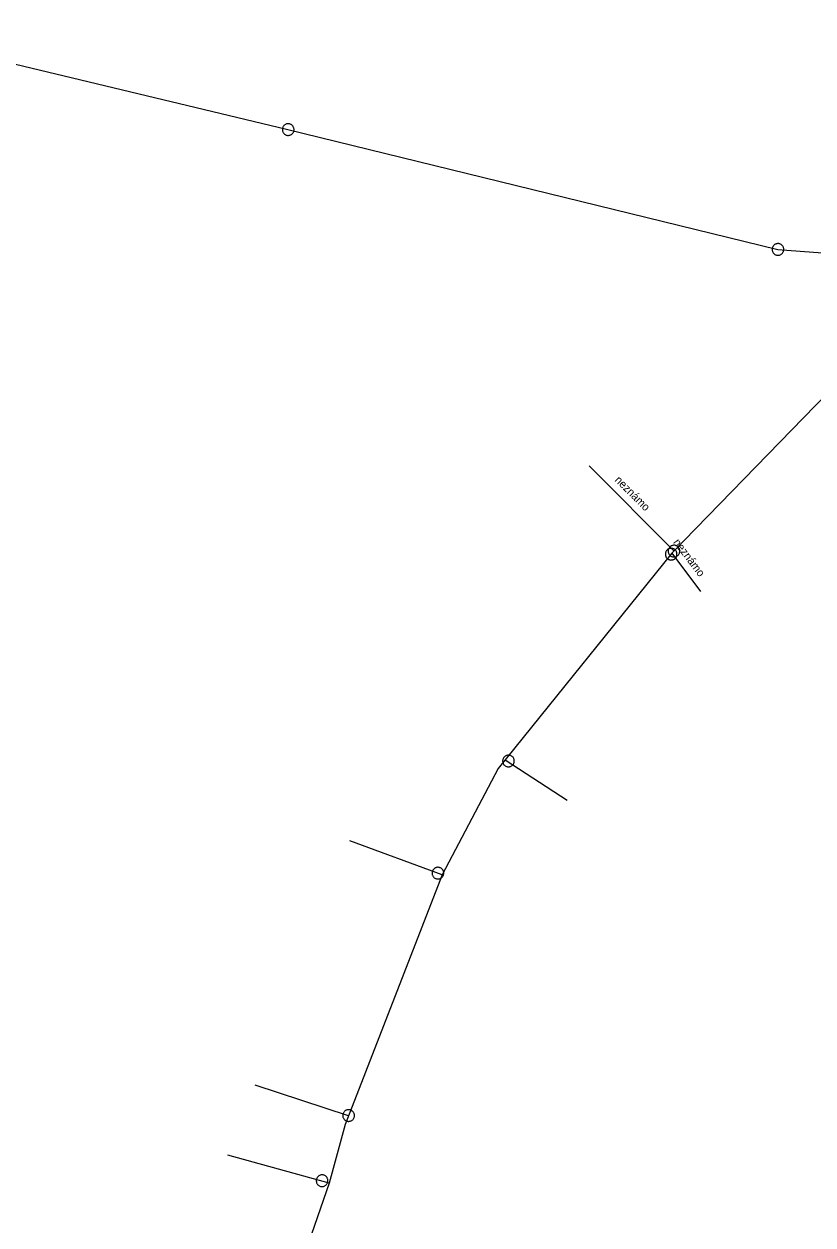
# Model space of a CAD drawing. Extents: x -741806 to -738704, y -1059275 to -1055387.
# Drawn here: x -740279.9 to -740220.6, y -1056767.8 to -1056677.8 of the extents above; entities that cross this region are included whole.
import ezdxf

# ---------------------------------------------------------------- set-up
doc = ezdxf.new("R2010")
doc.units = 0
doc.header["$LTSCALE"] = 0.4
for name, color, linetype, lineweight in [('2', 7, 'Continuous', 25), ('21', 7, 'Continuous', 13), ('3', 7, 'Continuous', 13), ('51', 7, 'Continuous', 13), ('52', 7, 'Continuous', 25)]:
    doc.layers.add(name, color=color, linetype=linetype, lineweight=lineweight)
doc.layers.add('54', color=7, linetype='Continuous')

msp = doc.modelspace()

# ---------------------------------------------------------------- linework, layer by layer
at = {"layer": '2'}
msp.add_lwpolyline([(-740339.62, -1056830), (-740315.66, -1056820.24), (-740310.64, -1056801.08), (-740301.43, -1056762.19), (-740297.32, -1056727.3), (-740286.155, -1056679.426), (-740260.146, -1056685.649), (-740223.28, -1056694.679), (-740203.5, -1056696.159)], dxfattribs=at)
at = {"layer": '21'}
for p, q in [((-740231.074, -1056717.3), (-740237.443, -1056710.901)), ((-740231.234, -1056717.463), (-740229.083, -1056720.327)), ((-740243.752, -1056732.952), (-740239.088, -1056735.977)), ((-740248.473, -1056741.574), (-740255.403, -1056739.044)), ((-740255.507, -1056759.67), (-740262.517, -1056757.362)), ((-740256.949, -1056764.72), (-740264.563, -1056762.608))]:
    msp.add_line(p, q, dxfattribs=at)
at = {"layer": '3'}
for points in [[(-740259.604, -1056685.794), (-740259.596, -1056685.75), (-740259.592, -1056685.704), (-740259.593, -1056685.658), (-740259.599, -1056685.613), (-740259.61, -1056685.568), (-740259.625, -1056685.525), (-740259.644, -1056685.484), (-740259.668, -1056685.444), (-740259.696, -1056685.408), (-740259.727, -1056685.375), (-740259.762, -1056685.345), (-740259.8, -1056685.318), (-740259.84, -1056685.297), (-740259.881, -1056685.278), (-740259.926, -1056685.266), (-740259.971, -1056685.257), (-740260.016, -1056685.254), (-740260.062, -1056685.254), (-740260.108, -1056685.26), (-740260.152, -1056685.271), (-740260.195, -1056685.286), (-740260.236, -1056685.305), (-740260.276, -1056685.329), (-740260.312, -1056685.356), (-740260.346, -1056685.388), (-740260.375, -1056685.423), (-740260.402, -1056685.46), (-740260.424, -1056685.501), (-740260.441, -1056685.543), (-740260.454, -1056685.587), (-740260.463, -1056685.631), (-740260.467, -1056685.677), (-740260.466, -1056685.723), (-740260.46, -1056685.769), (-740260.45, -1056685.813), (-740260.435, -1056685.856), (-740260.415, -1056685.897), (-740260.391, -1056685.937), (-740260.363, -1056685.973), (-740260.332, -1056686.006), (-740260.298, -1056686.036), (-740260.26, -1056686.063), (-740260.22, -1056686.085), (-740260.178, -1056686.103), (-740260.134, -1056686.115), (-740260.089, -1056686.124), (-740260.043, -1056686.128), (-740259.998, -1056686.127), (-740259.952, -1056686.121), (-740259.907, -1056686.11), (-740259.864, -1056686.095), (-740259.823, -1056686.076), (-740259.784, -1056686.052), (-740259.747, -1056686.025), (-740259.714, -1056685.993), (-740259.683, -1056685.958), (-740259.658, -1056685.921), (-740259.636, -1056685.88), (-740259.618, -1056685.838), (-740259.604, -1056685.795)], [(-740222.854, -1056694.783), (-740222.846, -1056694.739), (-740222.842, -1056694.693), (-740222.843, -1056694.647), (-740222.849, -1056694.602), (-740222.86, -1056694.557), (-740222.875, -1056694.514), (-740222.894, -1056694.473), (-740222.918, -1056694.433), (-740222.946, -1056694.397), (-740222.977, -1056694.364), (-740223.012, -1056694.334), (-740223.05, -1056694.307), (-740223.09, -1056694.286), (-740223.131, -1056694.267), (-740223.176, -1056694.255), (-740223.221, -1056694.246), (-740223.266, -1056694.243), (-740223.312, -1056694.243), (-740223.358, -1056694.249), (-740223.402, -1056694.26), (-740223.445, -1056694.275), (-740223.486, -1056694.294), (-740223.526, -1056694.318), (-740223.562, -1056694.345), (-740223.596, -1056694.377), (-740223.625, -1056694.412), (-740223.652, -1056694.449), (-740223.674, -1056694.49), (-740223.691, -1056694.532), (-740223.704, -1056694.576), (-740223.713, -1056694.62), (-740223.717, -1056694.666), (-740223.716, -1056694.712), (-740223.71, -1056694.758), (-740223.7, -1056694.802), (-740223.685, -1056694.845), (-740223.665, -1056694.886), (-740223.641, -1056694.926), (-740223.613, -1056694.962), (-740223.582, -1056694.995), (-740223.548, -1056695.025), (-740223.51, -1056695.052), (-740223.47, -1056695.074), (-740223.428, -1056695.092), (-740223.384, -1056695.104), (-740223.339, -1056695.113), (-740223.293, -1056695.117), (-740223.248, -1056695.116), (-740223.202, -1056695.11), (-740223.157, -1056695.099), (-740223.114, -1056695.084), (-740223.073, -1056695.065), (-740223.034, -1056695.041), (-740222.997, -1056695.014), (-740222.964, -1056694.982), (-740222.933, -1056694.947), (-740222.908, -1056694.91), (-740222.886, -1056694.869), (-740222.868, -1056694.827), (-740222.854, -1056694.784)]]:
    msp.add_lwpolyline(points, dxfattribs=at)
at = {"layer": '51'}
for points in [[(-740231.566, -1056717.875), (-740231.529, -1056717.902), (-740231.49, -1056717.925), (-740231.447, -1056717.944), (-740231.405, -1056717.958), (-740231.36, -1056717.967), (-740231.314, -1056717.972), (-740231.268, -1056717.971), (-740231.222, -1056717.967), (-740231.178, -1056717.957), (-740231.135, -1056717.943), (-740231.092, -1056717.924), (-740231.052, -1056717.902), (-740231.015, -1056717.875), (-740230.981, -1056717.844), (-740230.951, -1056717.81), (-740230.924, -1056717.773), (-740230.901, -1056717.733), (-740230.882, -1056717.692), (-740230.869, -1056717.648), (-740230.859, -1056717.602), (-740230.855, -1056717.557), (-740230.854, -1056717.512), (-740230.859, -1056717.466), (-740230.868, -1056717.421), (-740230.883, -1056717.377), (-740230.902, -1056717.335), (-740230.924, -1056717.297), (-740230.952, -1056717.259), (-740230.982, -1056717.225), (-740231.016, -1056717.194), (-740231.053, -1056717.168), (-740231.093, -1056717.145), (-740231.135, -1056717.126), (-740231.178, -1056717.112), (-740231.223, -1056717.103), (-740231.269, -1056717.098), (-740231.314, -1056717.098), (-740231.36, -1056717.102), (-740231.405, -1056717.113), (-740231.448, -1056717.127), (-740231.49, -1056717.145), (-740231.53, -1056717.168), (-740231.567, -1056717.195), (-740231.601, -1056717.225), (-740231.632, -1056717.26), (-740231.659, -1056717.297), (-740231.681, -1056717.337), (-740231.7, -1056717.378), (-740231.714, -1056717.422), (-740231.723, -1056717.467), (-740231.728, -1056717.513), (-740231.729, -1056717.558), (-740231.723, -1056717.604), (-740231.714, -1056717.648), (-740231.699, -1056717.692), (-740231.681, -1056717.734), (-740231.658, -1056717.773), (-740231.631, -1056717.811), (-740231.6, -1056717.845), (-740231.566, -1056717.874)], [(-740231.385, -1056717.618), (-740231.352, -1056717.648), (-740231.315, -1056717.675), (-740231.274, -1056717.698), (-740231.233, -1056717.715), (-740231.189, -1056717.729), (-740231.143, -1056717.738), (-740231.098, -1056717.742), (-740231.052, -1056717.742), (-740231.007, -1056717.735), (-740230.963, -1056717.726), (-740230.919, -1056717.711), (-740230.877, -1056717.692), (-740230.837, -1056717.669), (-740230.801, -1056717.641), (-740230.768, -1056717.61), (-740230.737, -1056717.575), (-740230.711, -1056717.538), (-740230.688, -1056717.498), (-740230.671, -1056717.456), (-740230.657, -1056717.412), (-740230.649, -1056717.367), (-740230.644, -1056717.322), (-740230.645, -1056717.276), (-740230.65, -1056717.23), (-740230.66, -1056717.185), (-740230.675, -1056717.142), (-740230.694, -1056717.101), (-740230.718, -1056717.061), (-740230.745, -1056717.025), (-740230.776, -1056716.99), (-740230.811, -1056716.961), (-740230.848, -1056716.935), (-740230.888, -1056716.912), (-740230.93, -1056716.894), (-740230.974, -1056716.881), (-740231.019, -1056716.871), (-740231.064, -1056716.868), (-740231.11, -1056716.868), (-740231.156, -1056716.874), (-740231.2, -1056716.884), (-740231.244, -1056716.899), (-740231.286, -1056716.918), (-740231.324, -1056716.942), (-740231.361, -1056716.968), (-740231.395, -1056717), (-740231.426, -1056717.034), (-740231.451, -1056717.072), (-740231.474, -1056717.111), (-740231.492, -1056717.154), (-740231.505, -1056717.198), (-740231.514, -1056717.243), (-740231.519, -1056717.288), (-740231.517, -1056717.334), (-740231.513, -1056717.379), (-740231.502, -1056717.424), (-740231.487, -1056717.468), (-740231.468, -1056717.509), (-740231.444, -1056717.549), (-740231.417, -1056717.585), (-740231.386, -1056717.618)], [(-740243.133, -1056733.285), (-740243.11, -1056733.246), (-740243.092, -1056733.204), (-740243.077, -1056733.16), (-740243.068, -1056733.116), (-740243.063, -1056733.07), (-740243.063, -1056733.024), (-740243.068, -1056732.979), (-740243.077, -1056732.934), (-740243.092, -1056732.891), (-740243.11, -1056732.849), (-740243.133, -1056732.809), (-740243.16, -1056732.771), (-740243.191, -1056732.737), (-740243.225, -1056732.707), (-740243.262, -1056732.68), (-740243.302, -1056732.657), (-740243.343, -1056732.638), (-740243.387, -1056732.624), (-740243.432, -1056732.615), (-740243.478, -1056732.611), (-740243.523, -1056732.611), (-740243.569, -1056732.615), (-740243.614, -1056732.625), (-740243.657, -1056732.639), (-740243.699, -1056732.658), (-740243.739, -1056732.681), (-740243.775, -1056732.707), (-740243.81, -1056732.739), (-740243.84, -1056732.773), (-740243.868, -1056732.809), (-740243.89, -1056732.849), (-740243.908, -1056732.89), (-740243.923, -1056732.935), (-740243.932, -1056732.979), (-740243.937, -1056733.025), (-740243.937, -1056733.071), (-740243.932, -1056733.116), (-740243.923, -1056733.161), (-740243.908, -1056733.204), (-740243.89, -1056733.246), (-740243.867, -1056733.286), (-740243.84, -1056733.323), (-740243.809, -1056733.357), (-740243.776, -1056733.388), (-740243.738, -1056733.414), (-740243.698, -1056733.438), (-740243.656, -1056733.456), (-740243.613, -1056733.47), (-740243.568, -1056733.479), (-740243.522, -1056733.484), (-740243.477, -1056733.484), (-740243.431, -1056733.48), (-740243.386, -1056733.47), (-740243.343, -1056733.456), (-740243.301, -1056733.437), (-740243.261, -1056733.414), (-740243.225, -1056733.387), (-740243.19, -1056733.356), (-740243.16, -1056733.322), (-740243.134, -1056733.285)], [(-740249.204, -1056741.307), (-740249.217, -1056741.35), (-740249.226, -1056741.395), (-740249.23, -1056741.441), (-740249.23, -1056741.486), (-740249.224, -1056741.532), (-740249.214, -1056741.577), (-740249.199, -1056741.62), (-740249.18, -1056741.662), (-740249.156, -1056741.701), (-740249.129, -1056741.737), (-740249.097, -1056741.771), (-740249.063, -1056741.802), (-740249.026, -1056741.828), (-740248.986, -1056741.85), (-740248.943, -1056741.868), (-740248.899, -1056741.881), (-740248.855, -1056741.89), (-740248.809, -1056741.894), (-740248.763, -1056741.893), (-740248.717, -1056741.887), (-740248.673, -1056741.877), (-740248.629, -1056741.863), (-740248.588, -1056741.843), (-740248.549, -1056741.82), (-740248.512, -1056741.792), (-740248.478, -1056741.76), (-740248.449, -1056741.726), (-740248.422, -1056741.688), (-740248.4, -1056741.648), (-740248.382, -1056741.606), (-740248.369, -1056741.563), (-740248.36, -1056741.518), (-740248.356, -1056741.472), (-740248.357, -1056741.427), (-740248.362, -1056741.381), (-740248.372, -1056741.336), (-740248.388, -1056741.293), (-740248.406, -1056741.251), (-740248.431, -1056741.213), (-740248.458, -1056741.176), (-740248.489, -1056741.142), (-740248.524, -1056741.112), (-740248.561, -1056741.086), (-740248.601, -1056741.063), (-740248.643, -1056741.046), (-740248.687, -1056741.032), (-740248.732, -1056741.024), (-740248.777, -1056741.019), (-740248.823, -1056741.02), (-740248.869, -1056741.026), (-740248.913, -1056741.036), (-740248.957, -1056741.05), (-740248.998, -1056741.07), (-740249.037, -1056741.093), (-740249.074, -1056741.121), (-740249.108, -1056741.153), (-740249.138, -1056741.187), (-740249.164, -1056741.225), (-740249.186, -1056741.265), (-740249.204, -1056741.306)], [(-740255.652, -1056760.044), (-740255.61, -1056760.058), (-740255.565, -1056760.068), (-740255.519, -1056760.073), (-740255.474, -1056760.073), (-740255.428, -1056760.069), (-740255.383, -1056760.059), (-740255.34, -1056760.045), (-740255.297, -1056760.027), (-740255.258, -1056760.004), (-740255.221, -1056759.977), (-740255.187, -1056759.947), (-740255.155, -1056759.913), (-740255.128, -1056759.876), (-740255.105, -1056759.837), (-740255.087, -1056759.795), (-740255.072, -1056759.751), (-740255.062, -1056759.707), (-740255.057, -1056759.661), (-740255.058, -1056759.615), (-740255.062, -1056759.569), (-740255.072, -1056759.525), (-740255.085, -1056759.481), (-740255.104, -1056759.439), (-740255.126, -1056759.399), (-740255.153, -1056759.362), (-740255.184, -1056759.328), (-740255.217, -1056759.297), (-740255.255, -1056759.27), (-740255.294, -1056759.247), (-740255.336, -1056759.228), (-740255.379, -1056759.214), (-740255.424, -1056759.204), (-740255.47, -1056759.199), (-740255.515, -1056759.199), (-740255.561, -1056759.204), (-740255.606, -1056759.213), (-740255.649, -1056759.227), (-740255.692, -1056759.245), (-740255.731, -1056759.269), (-740255.768, -1056759.295), (-740255.802, -1056759.325), (-740255.834, -1056759.359), (-740255.86, -1056759.396), (-740255.884, -1056759.435), (-740255.902, -1056759.478), (-740255.917, -1056759.521), (-740255.926, -1056759.566), (-740255.932, -1056759.611), (-740255.931, -1056759.657), (-740255.927, -1056759.703), (-740255.917, -1056759.748), (-740255.904, -1056759.791), (-740255.885, -1056759.833), (-740255.863, -1056759.873), (-740255.835, -1056759.91), (-740255.805, -1056759.945), (-740255.771, -1056759.975), (-740255.734, -1056760.002), (-740255.694, -1056760.025), (-740255.653, -1056760.043)], [(-740257.904, -1056764.41), (-740257.915, -1056764.454), (-740257.92, -1056764.499), (-740257.92, -1056764.546), (-740257.916, -1056764.591), (-740257.907, -1056764.636), (-740257.893, -1056764.68), (-740257.875, -1056764.722), (-740257.853, -1056764.762), (-740257.825, -1056764.798), (-740257.795, -1056764.833), (-740257.762, -1056764.864), (-740257.725, -1056764.892), (-740257.685, -1056764.915), (-740257.644, -1056764.934), (-740257.6, -1056764.948), (-740257.555, -1056764.958), (-740257.51, -1056764.964), (-740257.464, -1056764.964), (-740257.418, -1056764.959), (-740257.373, -1056764.95), (-740257.33, -1056764.936), (-740257.288, -1056764.919), (-740257.248, -1056764.895), (-740257.211, -1056764.869), (-740257.176, -1056764.838), (-740257.145, -1056764.804), (-740257.119, -1056764.768), (-740257.095, -1056764.728), (-740257.076, -1056764.687), (-740257.061, -1056764.643), (-740257.052, -1056764.599), (-740257.047, -1056764.554), (-740257.046, -1056764.507), (-740257.05, -1056764.462), (-740257.06, -1056764.417), (-740257.073, -1056764.373), (-740257.092, -1056764.332), (-740257.114, -1056764.291), (-740257.141, -1056764.255), (-740257.171, -1056764.22), (-740257.205, -1056764.189), (-740257.242, -1056764.161), (-740257.281, -1056764.139), (-740257.323, -1056764.119), (-740257.366, -1056764.105), (-740257.411, -1056764.095), (-740257.457, -1056764.09), (-740257.502, -1056764.089), (-740257.548, -1056764.094), (-740257.593, -1056764.103), (-740257.636, -1056764.117), (-740257.679, -1056764.135), (-740257.718, -1056764.158), (-740257.756, -1056764.184), (-740257.79, -1056764.215), (-740257.821, -1056764.249), (-740257.848, -1056764.285), (-740257.871, -1056764.325), (-740257.89, -1056764.366), (-740257.904, -1056764.409)]]:
    msp.add_lwpolyline(points, dxfattribs=at)
at = {"layer": '52'}
msp.add_lwpolyline([(-740175.489, -1056516.148), (-740182.237, -1056558.509), (-740182.283, -1056558.799), (-740184.208, -1056574.021), (-740186.954, -1056588.264), (-740195.633, -1056638.315), (-740197.478, -1056649.388), (-740200.254, -1056663.476), (-740207.839, -1056691.395), (-740209.772, -1056694), (-740210.063, -1056694.828), (-740213.269, -1056698.987), (-740231.234, -1056717.463), (-740244.285, -1056733.611), (-740248.473, -1056741.574), (-740255.759, -1056760.318), (-740256.949, -1056764.72), (-740259.395, -1056771.79), (-740264.607, -1056786.706), (-740265.408, -1056790.486), (-740270.787, -1056807.514), (-740272.432, -1056813.382), (-740275.537, -1056822.95), (-740275.601, -1056823.152)], dxfattribs=at)

# ---------------------------------------------------------------- texts
at = {"layer": '54'}
for rotation, p in [(315, (-740235.567, -1056712.017)), (307, (-740231.167, -1056716.651))]:
    msp.add_text('neznámo ', height=0.6, rotation=rotation, dxfattribs=at).set_placement(p)

doc.saveas('drawing.dxf')
